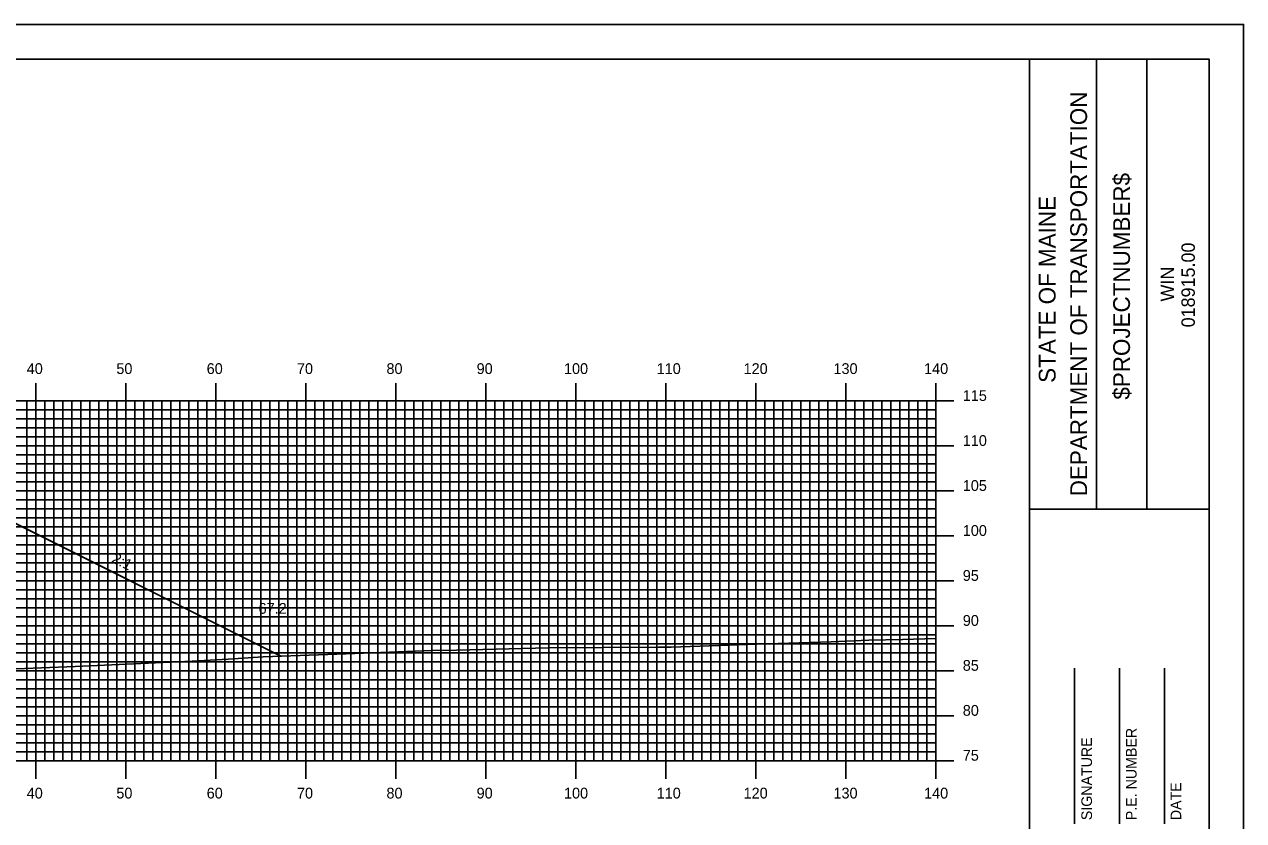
# Model space of a CAD drawing. Extents: x 1759823 to 1760167, y 442591 to 442811.
# Drawn here: x 1760027.9 to 1760163.4, y 442722 to 442810.5 of the extents above; entities that cross this region are included whole.
import ezdxf

# ---------------------------------------------------------------- set-up
doc = ezdxf.new("R2010")
doc.units = 0
for name, color, linetype in [('ANNOTATION', 7, 'Continuous'), ('BORDER', 7, 'Continuous'), ('D_Roadway_Centerline', 7, 'Continuous'), ('D_Roadway_SlopeLines', 7, 'Continuous'), ('D_Text_Standard', 7, 'Continuous'), ('H_V ANNOTATION', 7, 'Continuous'), ('MAJOR', 7, 'Continuous'), ('MINOR', 7, 'Continuous'), ('PLOT BOUNDARY', 7, 'Continuous'), ('S_Roadway_Centerline', 7, 'Continuous')]:
    doc.layers.add(name, color=color, linetype=linetype)

msp = doc.modelspace()

# ---------------------------------------------------------------- linework, layer by layer
at = {"layer": 'BORDER'}
for p, q in [((1760139.59, 442596.67), (1760139.59, 442806.67)), ((1760147.04, 442756.66), (1760147.04, 442806.66)), ((1760152.63, 442756.66), (1760152.63, 442806.66)), ((1760139.59, 442756.65), (1760159.59, 442756.65)), ((1760144.59, 442721.67), (1760144.59, 442738.97)), ((1760149.59, 442721.67), (1760149.59, 442738.97)), ((1760154.59, 442721.67), (1760154.59, 442738.97))]:
    msp.add_line(p, q, dxfattribs=at)
msp.add_lwpolyline([(1759839.59, 442596.67), (1760159.59, 442596.67), (1760159.59, 442806.67), (1759839.59, 442806.67)], close=True, dxfattribs=at)
at = {"layer": 'D_Roadway_Centerline'}
msp.add_lwpolyline([(1759923.86, 442736.88), (1759960.89, 442755.4), (1759966.19, 442758.04), (1759969.19, 442758.16), (1759977.19, 442758.48), (1759989.19, 442758.91), (1760001.19, 442759.35), (1760007.74, 442759.58), (1760015.74, 442759.26), (1760018.74, 442759.14), (1760023.49, 442756.77), (1760056.41, 442740.31)], dxfattribs=at)
at = {"layer": 'D_Roadway_SlopeLines'}
msp.add_lwpolyline([(1760018.74, 442759.14), (1760056.41, 442740.31)], dxfattribs=at)
at = {"layer": 'MAJOR'}
for p, q in [((1760029.19, 442770.67), (1760029.19, 442768.67)), ((1760039.19, 442770.67), (1760039.19, 442768.67)), ((1760049.19, 442770.67), (1760049.19, 442768.67)), ((1760059.19, 442770.67), (1760059.19, 442768.67)), ((1760069.19, 442770.67), (1760069.19, 442768.67)), ((1760079.19, 442770.67), (1760079.19, 442768.67)), ((1760089.19, 442770.67), (1760089.19, 442768.67)), ((1760099.19, 442770.67), (1760099.19, 442768.67)), ((1760109.19, 442770.67), (1760109.19, 442768.67)), ((1760119.19, 442770.67), (1760119.19, 442768.67)), ((1760129.19, 442770.67), (1760129.19, 442768.67)), ((1759849.19, 442768.67), (1760129.19, 442768.67)), ((1759849.19, 442768.67), (1760129.19, 442768.67)), ((1760029.19, 442728.67), (1760029.19, 442768.67)), ((1760039.19, 442728.67), (1760039.19, 442768.67)), ((1760049.19, 442728.67), (1760049.19, 442768.67)), ((1760059.19, 442728.67), (1760059.19, 442768.67)), ((1760069.19, 442728.67), (1760069.19, 442768.67)), ((1760079.19, 442728.67), (1760079.19, 442768.67)), ((1760089.19, 442728.67), (1760089.19, 442768.67)), ((1760099.19, 442728.67), (1760099.19, 442768.67)), ((1760109.19, 442728.67), (1760109.19, 442768.67)), ((1760119.19, 442728.67), (1760119.19, 442768.67)), ((1760131.19, 442768.67), (1760127.18, 442768.67)), ((1760129.19, 442728.67), (1760129.19, 442768.67)), ((1760129.19, 442728.67), (1760129.19, 442768.67)), ((1759849.19, 442763.67), (1760129.19, 442763.67)), ((1760131.19, 442763.67), (1760127.18, 442763.67)), ((1759849.19, 442758.67), (1760129.19, 442758.67)), ((1760131.19, 442758.67), (1760127.18, 442758.67)), ((1759849.19, 442753.67), (1760129.19, 442753.67)), ((1760131.19, 442753.67), (1760127.18, 442753.67)), ((1759849.19, 442748.67), (1760129.19, 442748.67)), ((1760131.19, 442748.67), (1760127.18, 442748.67)), ((1759849.19, 442743.67), (1760129.19, 442743.67)), ((1760131.19, 442743.67), (1760127.18, 442743.67)), ((1759849.19, 442738.67), (1760129.19, 442738.67)), ((1760131.19, 442738.67), (1760127.18, 442738.67)), ((1759849.19, 442733.67), (1760129.19, 442733.67)), ((1760131.19, 442733.67), (1760127.18, 442733.67)), ((1759849.19, 442728.67), (1760129.19, 442728.67)), ((1759849.19, 442728.67), (1760129.19, 442728.67)), ((1760029.19, 442726.66), (1760029.19, 442728.67)), ((1760039.19, 442726.66), (1760039.19, 442728.67)), ((1760049.19, 442726.66), (1760049.19, 442728.67)), ((1760059.19, 442726.66), (1760059.19, 442728.67)), ((1760069.19, 442726.66), (1760069.19, 442728.67)), ((1760079.19, 442726.66), (1760079.19, 442728.67)), ((1760089.19, 442726.66), (1760089.19, 442728.67)), ((1760099.19, 442726.66), (1760099.19, 442728.67)), ((1760109.19, 442726.66), (1760109.19, 442728.67)), ((1760119.19, 442726.66), (1760119.19, 442728.67)), ((1760131.19, 442728.67), (1760127.18, 442728.67)), ((1760129.19, 442726.66), (1760129.19, 442728.67))]:
    msp.add_line(p, q, dxfattribs=at)
at = {"layer": 'MINOR'}
for p, q in [((1760028.19, 442728.67), (1760028.19, 442768.67)), ((1760030.19, 442728.67), (1760030.19, 442768.67)), ((1760031.19, 442728.67), (1760031.19, 442768.67)), ((1760032.19, 442728.67), (1760032.19, 442768.67)), ((1760033.19, 442728.67), (1760033.19, 442768.67)), ((1760034.19, 442728.67), (1760034.19, 442768.67)), ((1760035.19, 442728.67), (1760035.19, 442768.67)), ((1760036.19, 442728.67), (1760036.19, 442768.67)), ((1760037.19, 442728.67), (1760037.19, 442768.67)), ((1760038.19, 442728.67), (1760038.19, 442768.67)), ((1760040.19, 442728.67), (1760040.19, 442768.67)), ((1760041.19, 442728.67), (1760041.19, 442768.67)), ((1760042.19, 442728.67), (1760042.19, 442768.67)), ((1760043.19, 442728.67), (1760043.19, 442768.67)), ((1760044.19, 442728.67), (1760044.19, 442768.67)), ((1760045.19, 442728.67), (1760045.19, 442768.67)), ((1760046.19, 442728.67), (1760046.19, 442768.67)), ((1760047.19, 442728.67), (1760047.19, 442768.67)), ((1760048.19, 442728.67), (1760048.19, 442768.67)), ((1760050.19, 442728.67), (1760050.19, 442768.67)), ((1760051.19, 442728.67), (1760051.19, 442768.67)), ((1760052.19, 442728.67), (1760052.19, 442768.67)), ((1760053.19, 442728.67), (1760053.19, 442768.67)), ((1760054.19, 442728.67), (1760054.19, 442768.67)), ((1760055.19, 442728.67), (1760055.19, 442768.67)), ((1760056.19, 442728.67), (1760056.19, 442768.67)), ((1760057.19, 442728.67), (1760057.19, 442768.67)), ((1760058.19, 442728.67), (1760058.19, 442768.67)), ((1760060.19, 442728.67), (1760060.19, 442768.67)), ((1760061.19, 442728.67), (1760061.19, 442768.67)), ((1760062.19, 442728.67), (1760062.19, 442768.67)), ((1760063.19, 442728.67), (1760063.19, 442768.67)), ((1760064.19, 442728.67), (1760064.19, 442768.67)), ((1760065.19, 442728.67), (1760065.19, 442768.67)), ((1760066.19, 442728.67), (1760066.19, 442768.67)), ((1760067.19, 442728.67), (1760067.19, 442768.67)), ((1760068.19, 442728.67), (1760068.19, 442768.67)), ((1760070.19, 442728.67), (1760070.19, 442768.67)), ((1760071.19, 442728.67), (1760071.19, 442768.67)), ((1760072.19, 442728.67), (1760072.19, 442768.67)), ((1760073.19, 442728.67), (1760073.19, 442768.67)), ((1760074.19, 442728.67), (1760074.19, 442768.67)), ((1760075.19, 442728.67), (1760075.19, 442768.67)), ((1760076.19, 442728.67), (1760076.19, 442768.67)), ((1760077.19, 442728.67), (1760077.19, 442768.67)), ((1760078.19, 442728.67), (1760078.19, 442768.67)), ((1760080.19, 442728.67), (1760080.19, 442768.67)), ((1760081.19, 442728.67), (1760081.19, 442768.67)), ((1760082.19, 442728.67), (1760082.19, 442768.67)), ((1760083.19, 442728.67), (1760083.19, 442768.67)), ((1760084.19, 442728.67), (1760084.19, 442768.67)), ((1760085.19, 442728.67), (1760085.19, 442768.67)), ((1760086.19, 442728.67), (1760086.19, 442768.67)), ((1760087.19, 442728.67), (1760087.19, 442768.67)), ((1760088.19, 442728.67), (1760088.19, 442768.67)), ((1760090.19, 442728.67), (1760090.19, 442768.67)), ((1760091.19, 442728.67), (1760091.19, 442768.67)), ((1760092.19, 442728.67), (1760092.19, 442768.67)), ((1760093.19, 442728.67), (1760093.19, 442768.67)), ((1760094.19, 442728.67), (1760094.19, 442768.67)), ((1760095.19, 442728.67), (1760095.19, 442768.67)), ((1760096.19, 442728.67), (1760096.19, 442768.67)), ((1760097.19, 442728.67), (1760097.19, 442768.67)), ((1760098.19, 442728.67), (1760098.19, 442768.67)), ((1760100.19, 442728.67), (1760100.19, 442768.67)), ((1760101.19, 442728.67), (1760101.19, 442768.67)), ((1760102.19, 442728.67), (1760102.19, 442768.67)), ((1760103.19, 442728.67), (1760103.19, 442768.67)), ((1760104.19, 442728.67), (1760104.19, 442768.67)), ((1760105.19, 442728.67), (1760105.19, 442768.67)), ((1760106.19, 442728.67), (1760106.19, 442768.67)), ((1760107.19, 442728.67), (1760107.19, 442768.67)), ((1760108.19, 442728.67), (1760108.19, 442768.67)), ((1760110.19, 442728.67), (1760110.19, 442768.67)), ((1760111.19, 442728.67), (1760111.19, 442768.67)), ((1760112.19, 442728.67), (1760112.19, 442768.67)), ((1760113.19, 442728.67), (1760113.19, 442768.67)), ((1760114.19, 442728.67), (1760114.19, 442768.67)), ((1760115.19, 442728.67), (1760115.19, 442768.67)), ((1760116.19, 442728.67), (1760116.19, 442768.67)), ((1760117.19, 442728.67), (1760117.19, 442768.67)), ((1760118.19, 442728.67), (1760118.19, 442768.67)), ((1760120.19, 442728.67), (1760120.19, 442768.67)), ((1760121.19, 442728.67), (1760121.19, 442768.67)), ((1760122.19, 442728.67), (1760122.19, 442768.67)), ((1760123.19, 442728.67), (1760123.19, 442768.67)), ((1760124.19, 442728.67), (1760124.19, 442768.67)), ((1760125.19, 442728.67), (1760125.19, 442768.67)), ((1760126.19, 442728.67), (1760126.19, 442768.67)), ((1760127.19, 442728.67), (1760127.19, 442768.67)), ((1760128.19, 442728.67), (1760128.19, 442768.67)), ((1759849.19, 442767.67), (1760129.19, 442767.67)), ((1759849.19, 442766.67), (1760129.19, 442766.67)), ((1760129.19, 442767.67), (1760127.18, 442767.67)), ((1760129.19, 442766.67), (1760127.18, 442766.67)), ((1759849.19, 442765.67), (1760129.19, 442765.67)), ((1760129.19, 442765.67), (1760127.18, 442765.67)), ((1759849.19, 442764.67), (1760129.19, 442764.67)), ((1760129.19, 442764.67), (1760127.18, 442764.67)), ((1759849.19, 442762.67), (1760129.19, 442762.67)), ((1760129.19, 442762.67), (1760127.18, 442762.67)), ((1759849.19, 442761.67), (1760129.19, 442761.67)), ((1760129.19, 442761.67), (1760127.18, 442761.67)), ((1759849.19, 442760.67), (1760129.19, 442760.67)), ((1759849.19, 442759.67), (1760129.19, 442759.67)), ((1760129.19, 442760.67), (1760127.18, 442760.67)), ((1760129.19, 442759.67), (1760127.18, 442759.67)), ((1759849.19, 442757.67), (1760129.19, 442757.67)), ((1760129.19, 442757.67), (1760127.18, 442757.67)), ((1759849.19, 442756.67), (1760129.19, 442756.67)), ((1759849.19, 442755.67), (1760129.19, 442755.67)), ((1760129.19, 442756.67), (1760127.18, 442756.67)), ((1760129.19, 442755.67), (1760127.18, 442755.67)), ((1759849.19, 442754.67), (1760129.19, 442754.67)), ((1760129.19, 442754.67), (1760127.18, 442754.67)), ((1759849.19, 442752.67), (1760129.19, 442752.67)), ((1759849.19, 442751.67), (1760129.19, 442751.67)), ((1760129.19, 442752.67), (1760127.18, 442752.67)), ((1760129.19, 442751.67), (1760127.18, 442751.67)), ((1759849.19, 442750.67), (1760129.19, 442750.67)), ((1760129.19, 442750.67), (1760127.18, 442750.67)), ((1759849.19, 442749.67), (1760129.19, 442749.67)), ((1760129.19, 442749.67), (1760127.18, 442749.67)), ((1759849.19, 442747.67), (1760129.19, 442747.67)), ((1760129.19, 442747.67), (1760127.18, 442747.67)), ((1759849.19, 442746.67), (1760129.19, 442746.67)), ((1760129.19, 442746.67), (1760127.18, 442746.67)), ((1759849.19, 442745.67), (1760129.19, 442745.67)), ((1759849.19, 442744.67), (1760129.19, 442744.67)), ((1760129.19, 442745.67), (1760127.18, 442745.67)), ((1760129.19, 442744.67), (1760127.18, 442744.67)), ((1759849.19, 442742.67), (1760129.19, 442742.67)), ((1760129.19, 442742.67), (1760127.18, 442742.67)), ((1759849.19, 442741.67), (1760129.19, 442741.67)), ((1759849.19, 442740.67), (1760129.19, 442740.67)), ((1760129.19, 442741.67), (1760127.18, 442741.67)), ((1760129.19, 442740.67), (1760127.18, 442740.67)), ((1759849.19, 442739.67), (1760129.19, 442739.67)), ((1760129.19, 442739.67), (1760127.18, 442739.67)), ((1759849.19, 442737.67), (1760129.19, 442737.67)), ((1759849.19, 442736.67), (1760129.19, 442736.67)), ((1760129.19, 442737.67), (1760127.18, 442737.67)), ((1760129.19, 442736.67), (1760127.18, 442736.67)), ((1759849.19, 442735.67), (1760129.19, 442735.67)), ((1760129.19, 442735.67), (1760127.18, 442735.67)), ((1759849.19, 442734.67), (1760129.19, 442734.67)), ((1760129.19, 442734.67), (1760127.18, 442734.67)), ((1759849.19, 442732.67), (1760129.19, 442732.67)), ((1760129.19, 442732.67), (1760127.18, 442732.67)), ((1759849.19, 442731.67), (1760129.19, 442731.67)), ((1760129.19, 442731.67), (1760127.18, 442731.67)), ((1759849.19, 442730.67), (1760129.19, 442730.67)), ((1760129.19, 442730.67), (1760127.18, 442730.67)), ((1759849.19, 442729.67), (1760129.19, 442729.67)), ((1760129.19, 442729.67), (1760127.18, 442729.67))]:
    msp.add_line(p, q, dxfattribs=at)
at = {"layer": 'PLOT BOUNDARY'}
msp.add_lwpolyline([(1759823.4, 442590.55), (1760163.4, 442590.55), (1760163.4, 442810.55), (1759823.4, 442810.55)], close=True, dxfattribs=at)
at = {"layer": 'S_Roadway_Centerline'}
msp.add_lwpolyline([(1760022.28, 442738.7), (1760033.54, 442739.13), (1760046.54, 442739.73), (1760050.55, 442739.98), (1760054.42, 442740.24), (1760063.66, 442740.57), (1760073.27, 442740.91), (1760075.92, 442740.98), (1760086.2, 442741.22), (1760098.37, 442741.28), (1760099.02, 442741.29), (1760099.79, 442741.3), (1760109.32, 442741.63), (1760117.58, 442741.9), (1760121.76, 442742.09), (1760125.48, 442742.16), (1760129.19, 442742.25)], dxfattribs=at)

# ---------------------------------------------------------------- texts
at = {"layer": 'ANNOTATION'}
msp.add_text('2:1', height=1.2, rotation=333.4349, dxfattribs=at).set_placement((1760037.51, 442750.79))
at = {"layer": 'BORDER'}
for s, height, p in [('DEPARTMENT OF TRANSPORTATION', 1.8635, (1760146, 442758.08)), ('$PROJECTNUMBER$', 1.8635, (1760150.77, 442768.82)), ('STATE OF MAINE', 1.8635, (1760142.5, 442770.69)), ('018915.00', 1.491, (1760157.98, 442776.86)), ('WIN', 1.491, (1760155.66, 442779.73)), ('SIGNATURE', 1.181, (1760146.55, 442722.06)), ('P.E. NUMBER', 1.1811, (1760151.51, 442722.06)), ('DATE', 1.181, (1760156.47, 442722.06))]:
    msp.add_text(s, height=height, rotation=90, dxfattribs=at).set_placement(p)
at = {"layer": 'D_Text_Standard'}
msp.add_text("67.2'", height=1.2, dxfattribs=at).set_placement((1760053.93, 442745.01))
at = {"layer": 'H_V ANNOTATION'}
for s, p in [('40', (1760028.16, 442771.67)), ('50', (1760038.12, 442771.67)), ('60', (1760048.16, 442771.67)), ('70', (1760058.19, 442771.67)), ('80', (1760068.14, 442771.67)), ('90', (1760078.16, 442771.67)), ('100', (1760087.87, 442771.67)), ('110', (1760098.17, 442771.67)), ('120', (1760107.83, 442771.67)), ('130', (1760117.82, 442771.67)), ('140', (1760127.89, 442771.67)), ('115', (1760132.19, 442768.67)), ('110', (1760132.19, 442763.67)), ('105', (1760132.19, 442758.67)), ('100', (1760132.19, 442753.67)), ('95', (1760132.19, 442748.67)), ('90', (1760132.19, 442743.67)), ('85', (1760132.19, 442738.67)), ('80', (1760132.19, 442733.67)), ('75', (1760132.19, 442728.67)), ('40', (1760028.16, 442724.47)), ('50', (1760038.12, 442724.47)), ('60', (1760048.16, 442724.47)), ('70', (1760058.19, 442724.47)), ('80', (1760068.14, 442724.47)), ('90', (1760078.16, 442724.47)), ('100', (1760087.87, 442724.47)), ('110', (1760098.17, 442724.47)), ('120', (1760107.83, 442724.47)), ('130', (1760117.82, 442724.47)), ('140', (1760127.89, 442724.47))]:
    msp.add_text(s, height=1.2, dxfattribs=at).set_placement(p)

doc.saveas('drawing.dxf')
